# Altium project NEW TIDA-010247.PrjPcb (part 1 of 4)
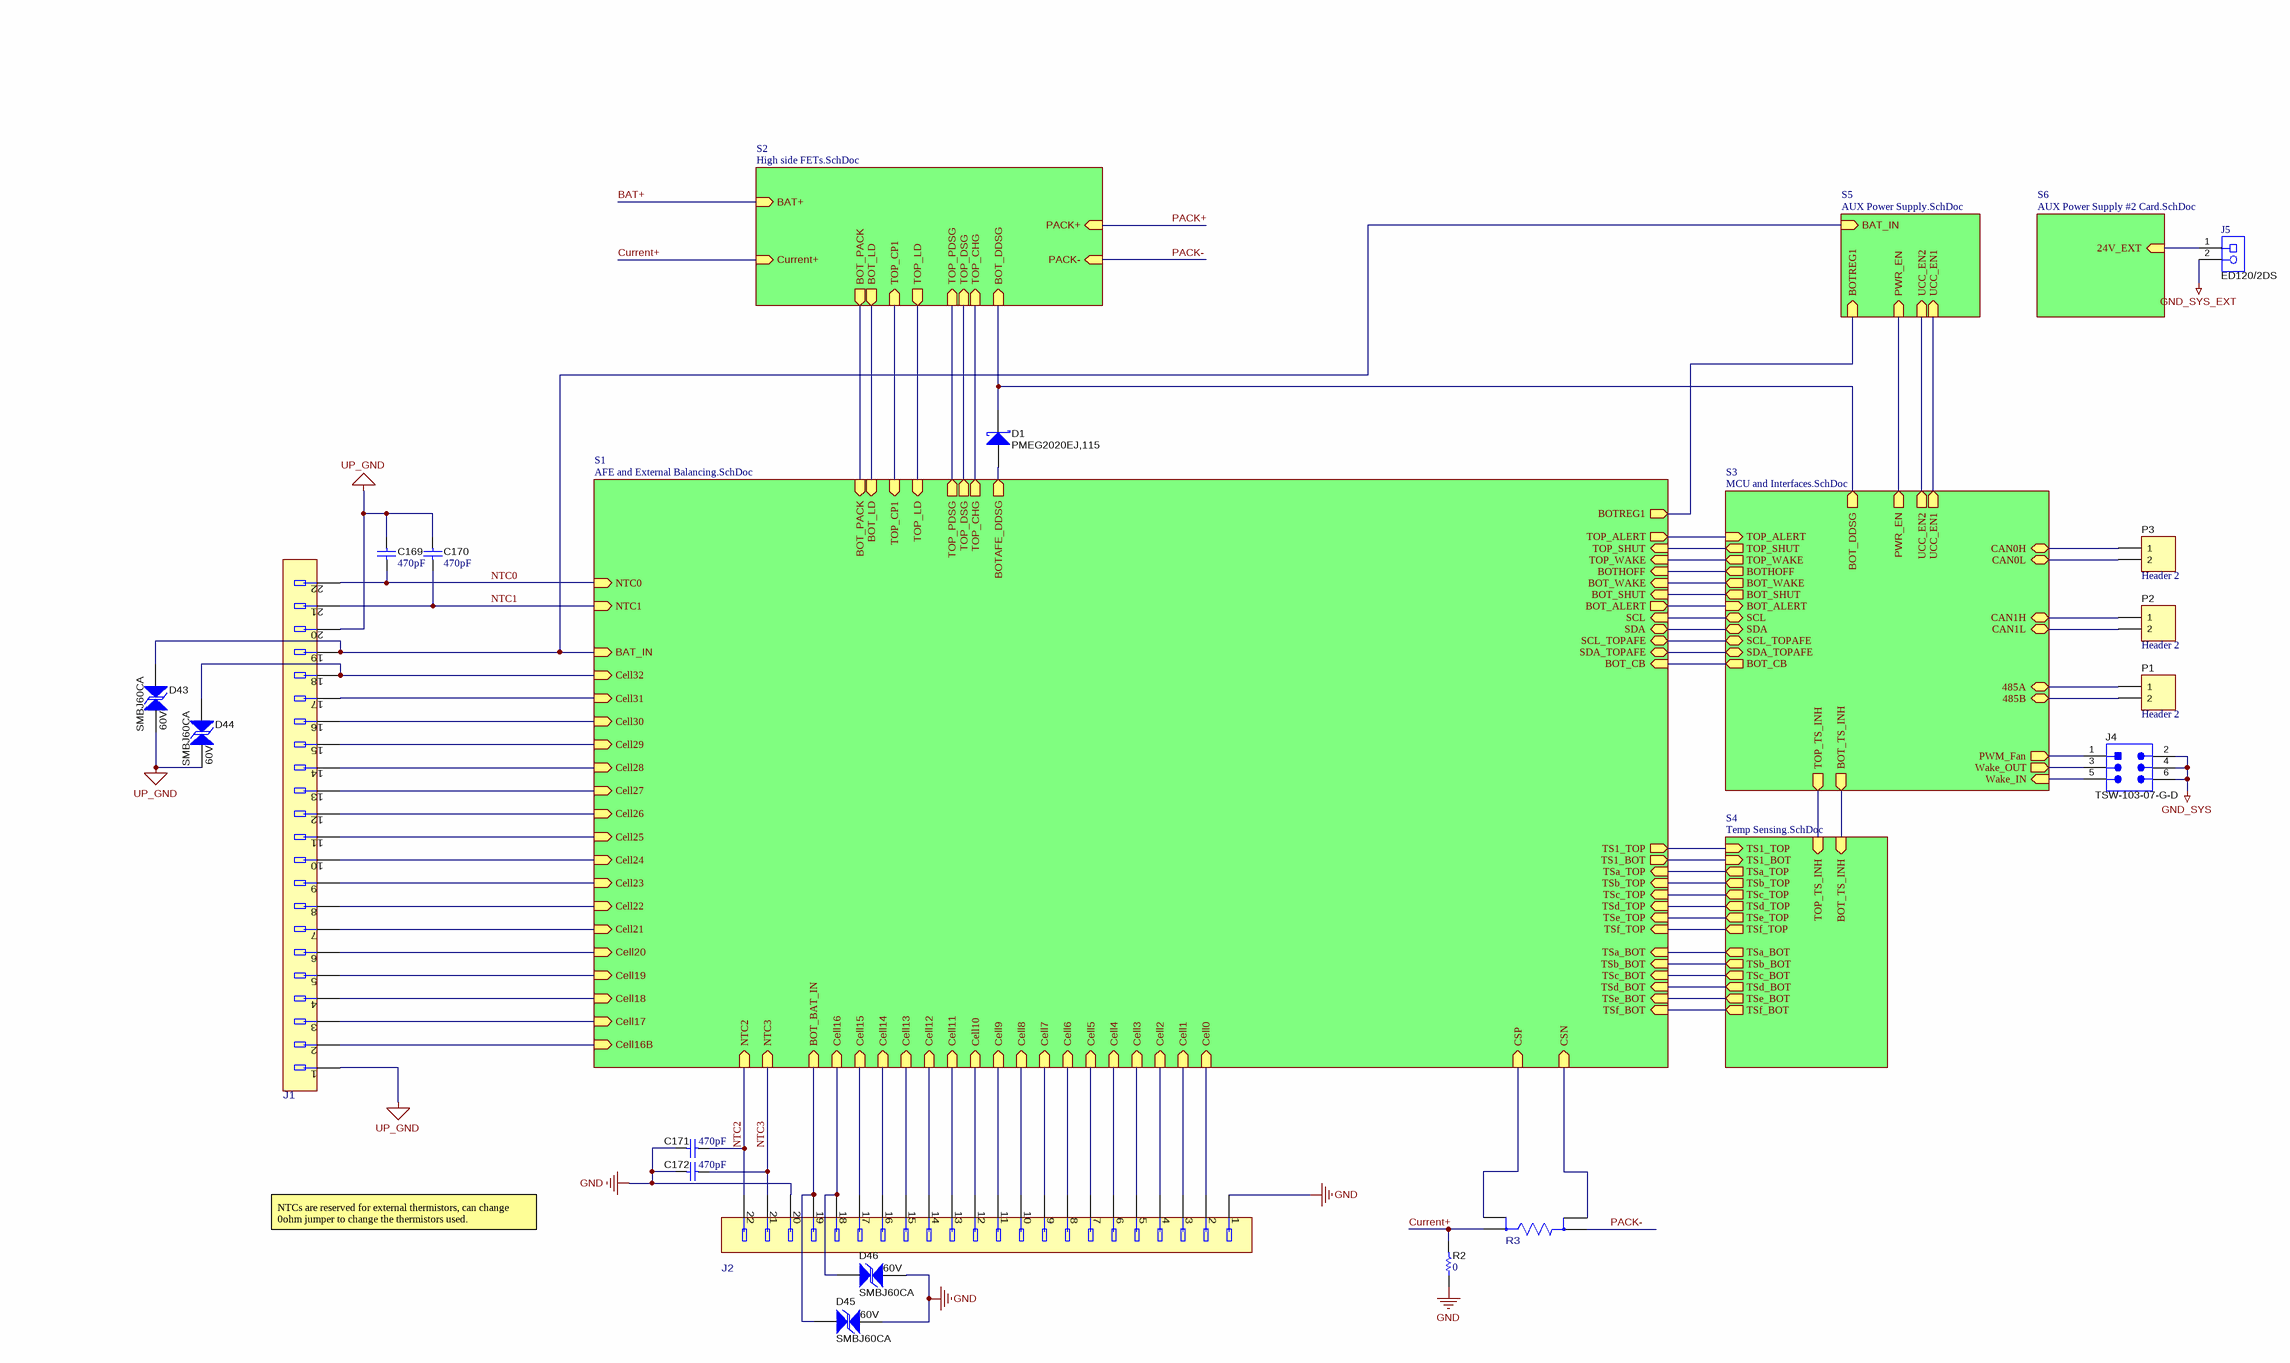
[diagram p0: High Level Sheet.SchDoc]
TID: TIDA-010247; TechSupport: http://www.ti.com/support; SCH_Rev: E1; PRJ_Title: 48v-1500v stackable BMU; PRJ_Number: TIDA-010247; PRJ_Engineer: Kian Lin; PRJ_Customer: Public Release; PCB_Rev: E1; PCB_Layout: Kian Lin; CopyrightYear: 2018
10 sheets, 812 parts. Net scope: hierarchical (ports join the sheet entries above them; power ports are global).
Board file: 32S BMU_BQ76972_CAN Stacking_V2.PcbDoc
Sheets:
  High Level Sheet.SchDoc
    S3 = MCU and Interfaces.SchDoc
    S1 = AFE and External Balancing.SchDoc
    S2 = High side FETs.SchDoc
    S5 = AUX Power Supply.SchDoc
    S4 = Temp Sensing.SchDoc
    U_EVM_Hardware = EVM_Hardware.SchDoc
    S6 = AUX Power Supply #2 Card.SchDoc
    S8 = Cell simulator.SchDoc
    S9 = Cover Sheet.SchDoc

## Sheet High Level Sheet.SchDoc
size A2; Date: Not shown in title block; ApprovedBy: Not shown in title block; CheckedBy: Not shown in title block; Author: Not shown in title block; CompanyName: Not shown in title block; Engineer: Not shown in title block; Organization: Not shown in title block; Address1: Not shown in title block; Address2: Not shown in title block; Address3: Not shown in title block; Address4: Not shown in title block; DocumentNumber: 1; Revision: Use project parameter SCH_Rev; SheetNumber: 1; SheetTotal: 10; PageSetup: Record=PageOptions¦CenterHorizontal=True¦CenterVertical=True¦PrintScale=0.69¦XCorrection=1.00¦YCorrection=1.00¦PrintKind=0¦BorderSize=5000000¦LeftOffset=0¦BottomOffset=0¦Orientation=2¦PaperLength=1000¦PaperWidth=1000¦Scale=100¦PaperSource=15¦PrintQuality=600¦MediaType=1¦DitherType=10¦PaperKind=Letter¦PrintScaleMode=1

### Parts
C169  ValueDisplayed: 470pF  [0201]  (hidden comment: GRM033R71C471KA01D)
C170  ValueDisplayed: 470pF  [0201]  (hidden comment: GRM033R71C471KA01D)
C171  ValueDisplayed: 470pF  [0201]  (hidden comment: GRM033R71C471KA01D)
C172  ValueDisplayed: 470pF  [0201]  (hidden comment: GRM033R71C471KA01D)
D1  PMEG2020EJ,115  [SOD-323F]  (no BOM)
D43  SMBJ60CA  value 60V  [SMB-Bi]
D44  SMBJ60CA  value 60V  [SMB-Bi]
D45  SMBJ60CA  value 60V  [SMB-Bi]
D46  SMBJ60CA  value 60V  [SMB-Bi]
J1  705550056  [FP-705550056_HDR22-MFG]  (value not drawn)
J2  705550056  [FP-705550056_HDR22-MFG]  (value not drawn)
J4  TSW-103-07-G-D  [TSW-103-07-G-D]
J5  ED120/2DS  [On-Shore_ED120_2DS]
P1  Header 2  [HDR1X2]  (no BOM)
P2  Header 2  [HDR1X2]  (no BOM)
P3  Header 2  [HDR1X2]  (no BOM)
R2  ValueDisplayed: 0  [0603]  (hidden comment: CRCW06030000Z0EA)
R3  SEWF3951FL300PT  [FP-SEWF3951FL300PT_3951-MFG]  (value not drawn)

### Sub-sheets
S1 = AFE and External Balancing.SchDoc: BAT_IN (in), BOT_LD (in), BOT_PACK (in), TOP_PDSG (out), TOP_DSG (out), TOP_CHG (out), TOP_LD (in), BOTAFE_DDSG (out), TOP_CP1 (in), SDA (bidir), SCL (in), BOT_SHUT (in), BOT_WAKE (in), BOTHOFF (in), TOP_WAKE (in), TOP_SHUT (in), SCL_TOPAFE (bidir), SDA_TOPAFE (bidir), TOP_ALERT (out), BOT_ALERT (out), Cell20 (in), Cell19 (in), Cell22 (in), Cell24 (in), Cell21 (in), Cell23 (in), Cell25 (in), Cell26 (in), Cell27 (in), Cell28 (in), Cell29 (in), Cell17 (in), Cell18 (in), Cell16B (in), NTC0 (in), NTC1 (in), Cell30 (in), Cell31 (in), Cell32 (in), BOT_BAT_IN (in), Cell15 (in), Cell3 (in), Cell6 (in), Cell11 (in), Cell7 (in), Cell12 (in), Cell9 (in), Cell4 (in), Cell8 (in), Cell5 (in), Cell13 (in), Cell14 (in), Cell16 (in), Cell10 (in), Cell0 (in), Cell1 (in), Cell2 (in), NTC3 (in), NTC2 (in), CSP (in), CSN (in), BOTREG1 (out), TSa_TOP (in), TS1_TOP (out), TS1_BOT (out), TSe_BOT (in), TSf_BOT (in), TSd_BOT (in), TSc_BOT (in), TSb_BOT (in), TSa_BOT (in), TSc_TOP (in), TSb_TOP (in), TSf_TOP (in), TSd_TOP (in), TSe_TOP (in), BOT_CB (in)
S2 = High side FETs.SchDoc: BAT+ (in), Current+ (in), PACK+ (in), PACK- (in), BOT_LD (out), BOT_PACK (out), TOP_DSG (in), TOP_LD (out), TOP_CHG (in), BOT_DDSG (in), TOP_PDSG (in), TOP_CP1 (in)
S3 = MCU and Interfaces.SchDoc: PWR_EN (out), BOT_DDSG (out), TOP_ALERT (in), TOP_SHUT (out), TOP_WAKE (out), BOTHOFF (out), BOT_WAKE (out), BOT_SHUT (out), SCL_TOPAFE (bidir), SDA_TOPAFE (bidir), PWM_Fan (out), Wake_IN (in), Wake_OUT (out), SCL (bidir), SDA (bidir), BOT_TS_INH (out), TOP_TS_INH (out), BOT_ALERT (in), CAN0H (bidir), CAN0L (bidir), CAN1H (bidir), CAN1L (bidir), 485A (bidir), 485B (bidir), BOT_CB (out), UCC_EN2 (out), UCC_EN1 (out)
S4 = Temp Sensing.SchDoc: TOP_TS_INH (in), BOT_TS_INH (in), TSa_TOP (out), TSb_TOP (out), TSc_TOP (out), TSd_TOP (out), TSe_TOP (out), TSf_TOP (out), TSa_BOT (out), TSb_BOT (out), TSc_BOT (out), TSd_BOT (out), TSe_BOT (out), TSf_BOT (out), TS1_TOP (in), TS1_BOT (in)
S5 = AUX Power Supply.SchDoc: BAT_IN (in), PWR_EN (in), UCC_EN1 (in), UCC_EN2 (in), BOTREG1 (in)
S6 = AUX Power Supply #2 Card.SchDoc: 24V_EXT (in)
S8 = Cell simulator.SchDoc: no entries
S9 = Cover Sheet.SchDoc: no entries
U_EVM_Hardware = EVM_Hardware.SchDoc: no entries

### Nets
GND: C171.2 C172.2 D45.1 D46.1 J2.1 J2.20 R2.1
GND_SYS: J4.2 J4.4 J4.6
GND_SYS_EXT: J5.2
UP_GND: C169.2 C170.2 D43.1 D44.1 J1.1 J1.20
5V: sheet S1/BOTREG1, sheet S5/BOTREG1
24V_EXT: J5.1 ; sheet S6/24V_EXT
485A: P1.1 ; sheet S3/485A
485B: P1.2 ; sheet S3/485B
BAT_IN: D43.2 J1.19 ; sheet S1/BAT_IN, sheet S5/BAT_IN
BOT_ALERT: sheet S3/BOT_ALERT, sheet S1/BOT_ALERT
BOT_BAT_IN: D45.2 J2.19 ; sheet S1/BOT_BAT_IN
BOT_CB: sheet S3/BOT_CB, sheet S1/BOT_CB
BOT_DDSG: D1.1(K) ; sheet S3/BOT_DDSG, sheet S2/BOT_DDSG
BOT_INH: sheet S3/BOT_TS_INH, sheet S4/BOT_TS_INH
BOT_LD: sheet S1/BOT_LD, sheet S2/BOT_LD
BOT_PACK: sheet S1/BOT_PACK, sheet S2/BOT_PACK
BOT_SHUT: sheet S3/BOT_SHUT, sheet S1/BOT_SHUT
BOT_WAKE: sheet S3/BOT_WAKE, sheet S1/BOT_WAKE
BOTAFE_DDSG: D1.2(A) ; sheet S1/BOTAFE_DDSG
BOTHOFF: sheet S3/BOTHOFF, sheet S1/BOTHOFF
CAN0H: P3.1 ; sheet S3/CAN0H
CAN0L: P3.2 ; sheet S3/CAN0L
CAN1H: P2.1 ; sheet S3/CAN1H
CAN1L: P2.2 ; sheet S3/CAN1L
Cell0: J2.2 ; sheet S1/Cell0
Cell1: J2.3 ; sheet S1/Cell1
Cell2: J2.4 ; sheet S1/Cell2
Cell3: J2.5 ; sheet S1/Cell3
Cell4: J2.6 ; sheet S1/Cell4
Cell5: J2.7 ; sheet S1/Cell5
Cell6: J2.8 ; sheet S1/Cell6
Cell7: J2.9 ; sheet S1/Cell7
Cell8: J2.10 ; sheet S1/Cell8
Cell9: J2.11 ; sheet S1/Cell9
Cell10: J2.12 ; sheet S1/Cell10
Cell11: J2.13 ; sheet S1/Cell11
Cell12: J2.14 ; sheet S1/Cell12
Cell13: J2.15 ; sheet S1/Cell13
Cell14: J2.16 ; sheet S1/Cell14
Cell15: J2.17 ; sheet S1/Cell15
Cell16: D46.2 J2.18 ; sheet S1/Cell16
Cell16B: J1.2 ; sheet S1/Cell16B
Cell17: J1.3 ; sheet S1/Cell17
Cell18: J1.4 ; sheet S1/Cell18
Cell19: J1.5 ; sheet S1/Cell19
Cell20: J1.6 ; sheet S1/Cell20
Cell21: J1.7 ; sheet S1/Cell21
Cell22: J1.8 ; sheet S1/Cell22
Cell23: J1.9 ; sheet S1/Cell23
Cell24: J1.10 ; sheet S1/Cell24
Cell25: J1.11 ; sheet S1/Cell25
Cell26: J1.12 ; sheet S1/Cell26
Cell27: J1.13 ; sheet S1/Cell27
Cell28: J1.14 ; sheet S1/Cell28
Cell29: J1.15 ; sheet S1/Cell29
Cell30: J1.16 ; sheet S1/Cell30
Cell31: J1.17 ; sheet S1/Cell31
Cell32: D44.2 J1.18 ; sheet S1/Cell32
CSN: R3.4 ; sheet S1/CSN
CSP: R3.3 ; sheet S1/CSP
Current+: R2.2 R3.1 ; sheet S2/Current+
EN: sheet S3/PWR_EN, sheet S5/PWR_EN
NTC0: C169.1 J1.22 ; sheet S1/NTC0
NTC1: C170.1 J1.21 ; sheet S1/NTC1
NTC2: C171.1 J2.22 ; sheet S1/NTC2
NTC3: C172.1 J2.21 ; sheet S1/NTC3
PACK-: R3.2 ; sheet S2/PACK-
PWM_Fan: J4.1 ; sheet S3/PWM_Fan
SCL: sheet S3/SCL, sheet S1/SCL
SCL_TOPAFE: sheet S3/SCL_TOPAFE, sheet S1/SCL_TOPAFE
SDA: sheet S3/SDA, sheet S1/SDA
SDA_TOPAFE: sheet S3/SDA_TOPAFE, sheet S1/SDA_TOPAFE
TOP_ALERT: sheet S3/TOP_ALERT, sheet S1/TOP_ALERT
TOP_CHG: sheet S1/TOP_CHG, sheet S2/TOP_CHG
TOP_CP1: sheet S1/TOP_CP1, sheet S2/TOP_CP1
TOP_DSG: sheet S1/TOP_DSG, sheet S2/TOP_DSG
TOP_LD: sheet S1/TOP_LD, sheet S2/TOP_LD
TOP_PDSG: sheet S1/TOP_PDSG, sheet S2/TOP_PDSG
TOP_SHUT: sheet S3/TOP_SHUT, sheet S1/TOP_SHUT
TOP_TS_INH: sheet S3/TOP_TS_INH, sheet S4/TOP_TS_INH
TOP_WAKE: sheet S3/TOP_WAKE, sheet S1/TOP_WAKE
TS1_BOT: sheet S1/TS1_BOT, sheet S4/TS1_BOT
TS1_TOP: sheet S1/TS1_TOP, sheet S4/TS1_TOP
TSa_BOT: sheet S1/TSa_BOT, sheet S4/TSa_BOT
TSa_TOP: sheet S1/TSa_TOP, sheet S4/TSa_TOP
TSb_BOT: sheet S1/TSb_BOT, sheet S4/TSb_BOT
TSb_TOP: sheet S1/TSb_TOP, sheet S4/TSb_TOP
TSc_BOT: sheet S1/TSc_BOT, sheet S4/TSc_BOT
TSc_TOP: sheet S1/TSc_TOP, sheet S4/TSc_TOP
TSd_BOT: sheet S1/TSd_BOT, sheet S4/TSd_BOT
TSd_TOP: sheet S1/TSd_TOP, sheet S4/TSd_TOP
TSe_BOT: sheet S1/TSe_BOT, sheet S4/TSe_BOT
TSe_TOP: sheet S1/TSe_TOP, sheet S4/TSe_TOP
TSf_BOT: sheet S1/TSf_BOT, sheet S4/TSf_BOT
TSf_TOP: sheet S1/TSf_TOP, sheet S4/TSf_TOP
UCC_EN1: sheet S3/UCC_EN1, sheet S5/UCC_EN1
UCC_EN2: sheet S3/UCC_EN2, sheet S5/UCC_EN2
Wake_IN: J4.5 ; sheet S3/Wake_IN
Wake_OUT: J4.3 ; sheet S3/Wake_OUT

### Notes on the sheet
- NTCs are reserved for external thermistors, can change 0ohm jumper to change the thermistors used.

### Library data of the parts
C169-C172 = CMP-0009758-1: CAP, CERM, 470 pF, 16 V, +/- 10%, X7R, 0201; Manufacturer: MuRata; TaMin_C: -55°C; Polarized: N; SizeAreaWB_mm2: 2.08; Value1: Unknown; U/M: EA; Value: 470pF; TaMax_C: 125°C; SizeZ_mm: 0.26; SizeX_mm: 0.6; SizeY_mm: 0.3; Value2: 16V; SizeArea_mm2: 0.18; VDC_V: ; AEC Category: Q200
D1 = CMP-0077073-2: Diode, Schottky, 20 V, 2 A, SOD-323F; Manufacturer: Nexperia; Value2: 0.525V; Value1: 2A; Green_REACh: Incomplete; Value: 20V; SizeX_mm: 2.5; SizeAreaWB_mm2: 7.875; AEC Category: Q101; Vf_V: 525mV; SizeY_mm: 1.25; SizeArea_mm2: 3.125; SizeZ_mm: 0.8; Green_Lifecycle: Not Set; TJmax_C: 150°C; AEC Qualified: N
D43-D46 = CMP-0006055-3: Diode, TVS, Bi, 60V， SMB; Manufacturer: Littelfuse; AEC Category: Q101; AEC Qualified: N; Vbr_Max: 62.7V; Value1: 600W; Vbr_Min: 56.7V; Vc: 82.4V; VRWM: 51V; Ipp: 7.3A
J1 J2 = CMP-0087165-1: Connector Header Through Hole, Right Angle 22 position 0.100" (2.54mm); Manufacturer: Molex; Voltage_V: 250V; Current_A: 3A; ContactFinish: Gold,Nickel; Row_Count: 1
J4 = CMP-0075406-2: Header, 100mil, 3x2, Gold, TH; Manufacturer: Samtec; Pitch_mm: 2.54; Cert_VDE: N; Gender: Male; Cert_CSA: Y; Voltage_V: 550V; Green_REACh: Passed; Current_A: 6.3A; Green_Lifecycle: Active; Row_Count: 2
J5 = CMP-0074910-1: Terminal Block, 5.08 mm, 2x1, Brass, TH; Manufacturer: On-Shore Technology; Cert_VDE: Y; CNHeader: False; Current_A: 15A; Green_Lifecycle: Not Set; Shrouded: N; Gender: Female; Green_REACh: Incomplete; Voltage_V: 300V; Row_Count: 1; Pitch_mm: 5.08; CT: True
P1-P3 = Header 2: Header, 2-Pin
R2 = CMP-0025697-4: RES, 0, 5%, 0.1 W, AEC-Q200 Grade 0, 0603; Manufacturer: Vishay-Dale; Power_W: 100mW; TempCo: 200 ppm/C; Value_Code: 0000; Value: 0; EIA_Code: E24; SizeX_mm: 1.6; SizeY_mm: 0.8; SizeZ_mm: 1; Value2: 0.1W; SizeArea_mm2: 1.28; AEC Qualified: Y; VDC_V: 75V; AEC Category: Q200
R3 = CMP-0122174-1: High-Precision Low-TCR Alloy Current Sensing Resistor 0.3mOhm 1% 25ppm/°C 15W 3951; Manufacturer: C&B ELECTRONICS; AEC Grade: Grade 0; AEC Qualified: Yes; Res_ohm: 300µ; SizeZ_mm: 2.6mm; Value: 300µ

## Sheet MCU and Interfaces.SchDoc
size A2; Date: Not shown in title block; ApprovedBy: Not shown in title block; CheckedBy: Not shown in title block; Author: Not shown in title block; CompanyName: Not shown in title block; Engineer: Not shown in title block; Organization: Not shown in title block; Address1: Not shown in title block; Address2: Not shown in title block; Address3: Not shown in title block; Address4: Not shown in title block; DocumentNumber: 1; Revision: Use project parameter SCH_Rev; SheetNumber: 4; SheetTotal: 10; PageSetup: Record=PageOptions¦CenterHorizontal=True¦CenterVertical=True¦PrintScale=0.69¦XCorrection=1.00¦YCorrection=1.00¦PrintKind=0¦BorderSize=5000000¦LeftOffset=0¦BottomOffset=0¦Orientation=2¦PaperLength=1000¦PaperWidth=1000¦Scale=100¦PaperSource=15¦PrintQuality=600¦MediaType=1¦DitherType=10¦PaperKind=Letter¦PrintScaleMode=1
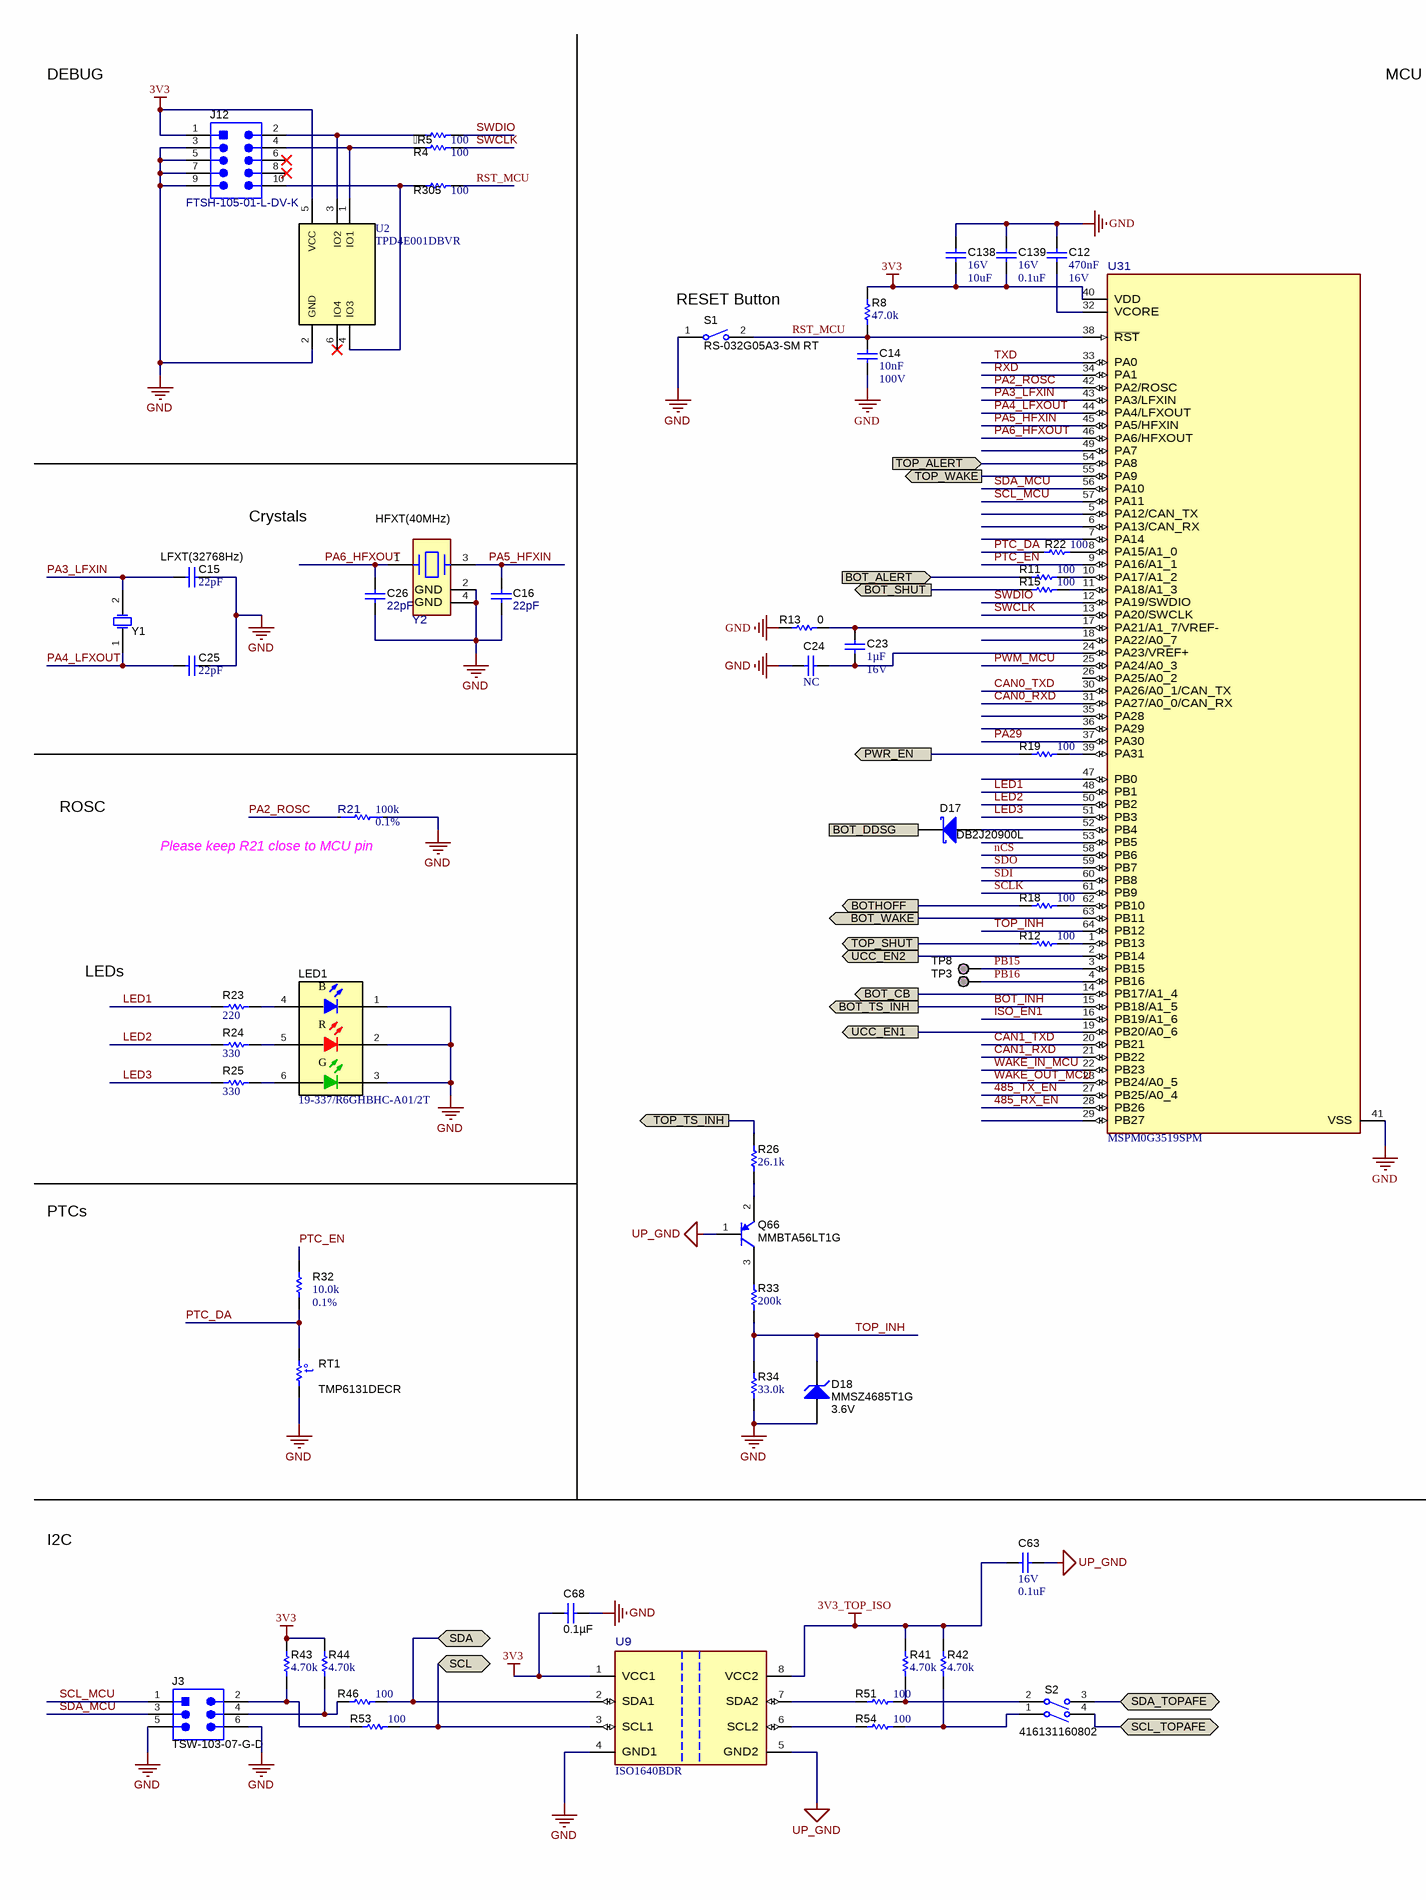
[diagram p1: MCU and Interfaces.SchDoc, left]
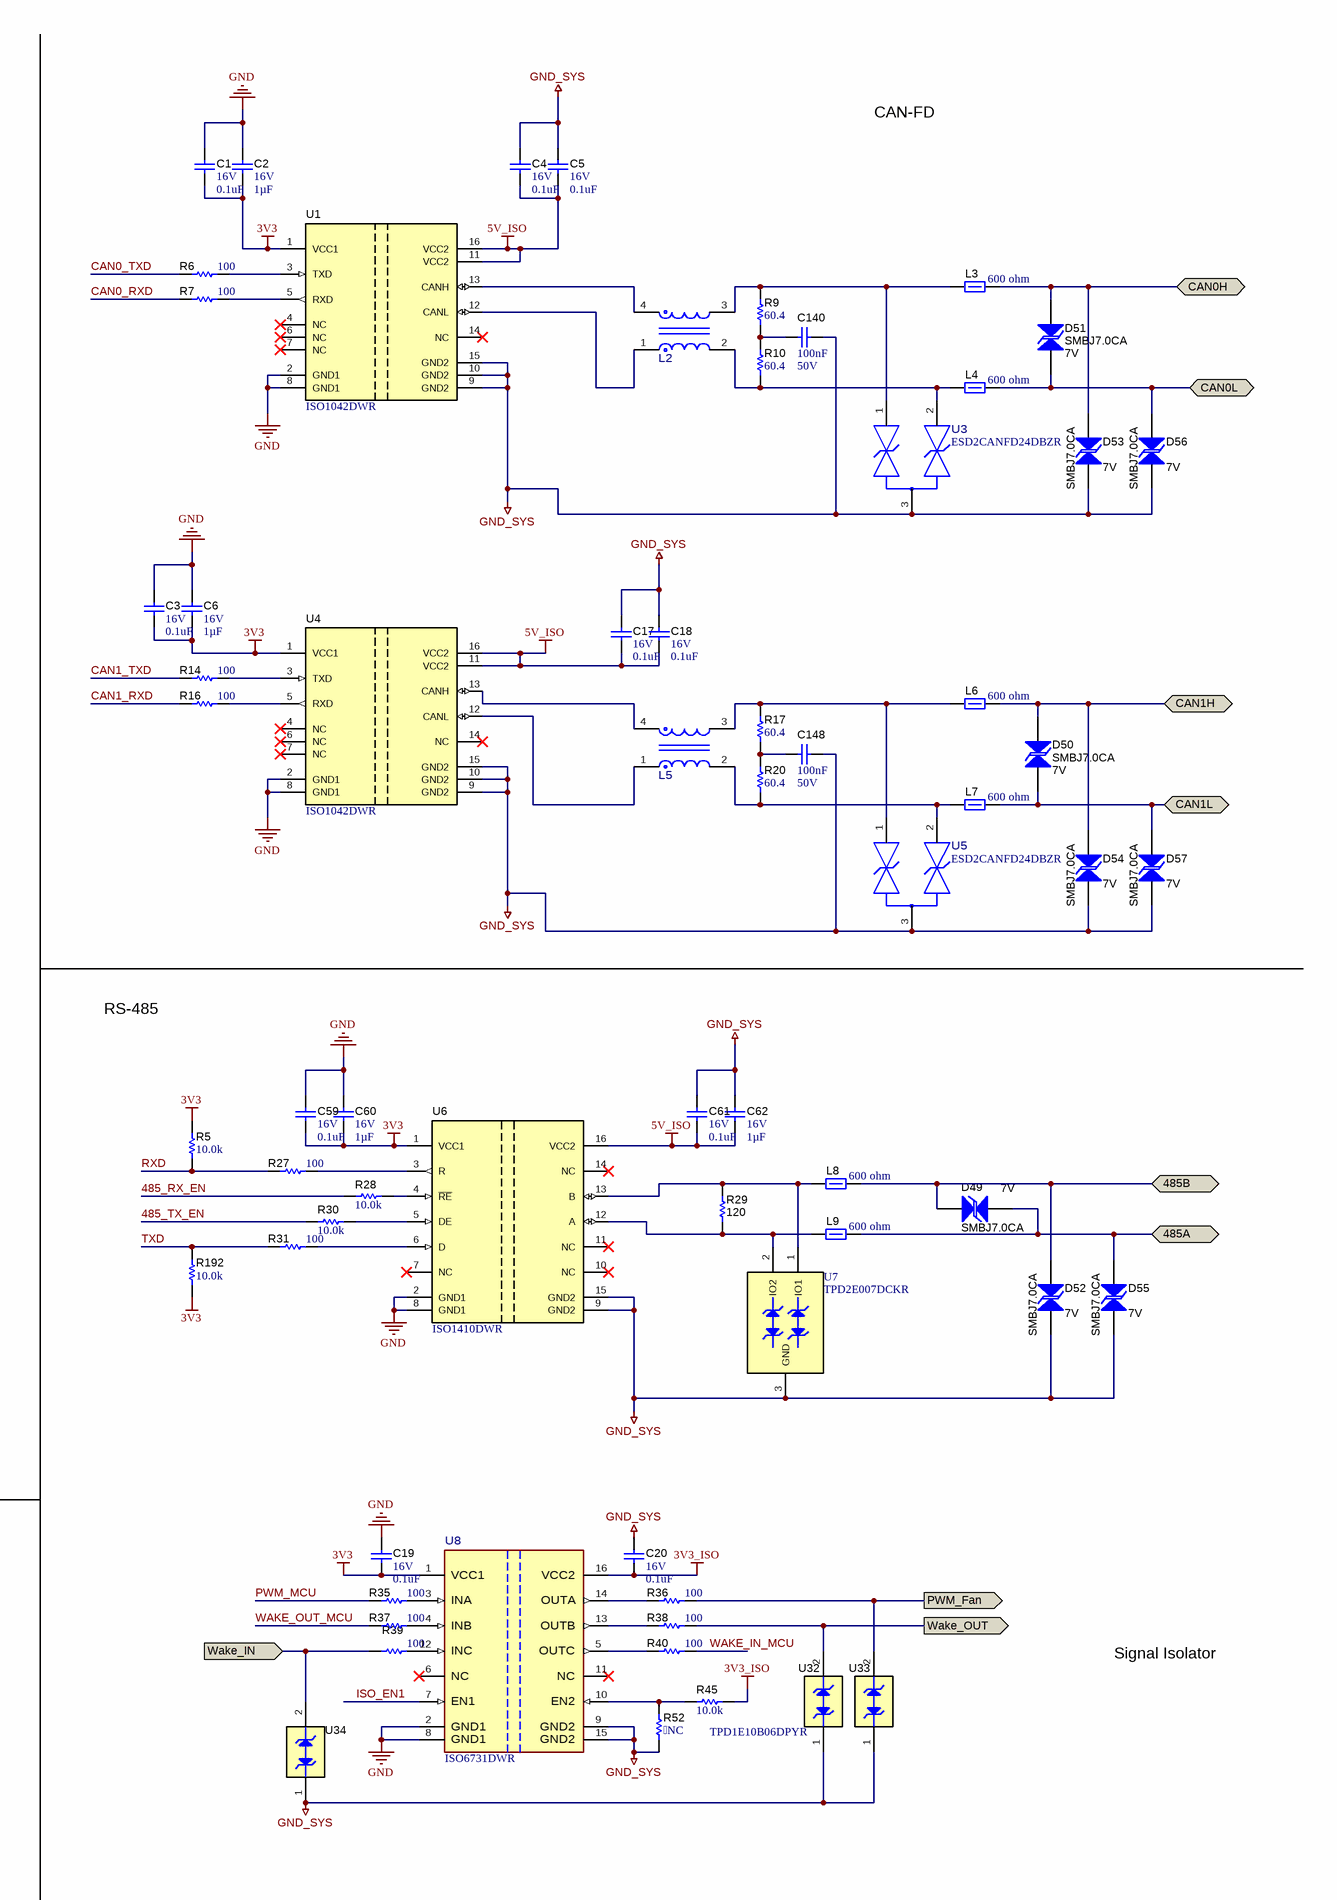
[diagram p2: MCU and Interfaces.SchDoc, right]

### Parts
R5  ValueDisplayed: 100  [0603]  (hidden comment: CRCW0603100RFKEA)
C1  VDC_V: 16V  ValueDisplayed: 0.1uF  [0603]  (hidden comment: GRM188R61C104KA01D)
C2  VDC_V: 16V  ValueDisplayed: 1µF  [0603]  (hidden comment: CC0603MRX5R7BB105)
C3  VDC_V: 16V  ValueDisplayed: 0.1uF  [0603]  (hidden comment: EMK107BBJ106MA-T)
C4  VDC_V: 16V  ValueDisplayed: 0.1uF  [0603]  (hidden comment: GRM188R61C104KA01D)
C5  VDC_V: 16V  ValueDisplayed: 0.1uF  [0603]  (hidden comment: GRM188R61C104KA01D)
C6  VDC_V: 16V  ValueDisplayed: 1µF  [0603]  (hidden comment: EMK107BBJ106MA-T)
C12  Cap_F: 470nF  VDC_V: 16V  [0603]  (hidden comment: GCM188R71C474KA55D)
C14  Cap_F: 10nF  VDC_V: 100V  [0603]  (hidden comment: C0603X103K1RACTU)
C15  ValueDisplayed: 22pF  [0402]  (hidden comment: GRM1555C1H220JA01D)
C16  ValueDisplayed: 22pF  [0402]  (hidden comment: GRM1555C1H220JA01D)
C17  VDC_V: 16V  ValueDisplayed: 0.1uF  [0603]  (hidden comment: GRM188R61C104KA01D)
C18  VDC_V: 16V  ValueDisplayed: 0.1uF  [0603]  (hidden comment: GRM188R61C104KA01D)
C19  VDC_V: 16V  ValueDisplayed: 0.1uF  [0603]  (hidden comment: GRM188R61C104KA01D)
C20  VDC_V: 16V  ValueDisplayed: 0.1uF  [0603]  (hidden comment: GRM188R61C104KA01D)
C23  Cap_F: 1µF  VDC_V: 16V  [0603]  (hidden comment: GCM188R71C105KA64J)
C24  ValueDisplayed: NC  [0603]  (hidden comment: C1608X5R1E105K080AC)  (no BOM)
C25  ValueDisplayed: 22pF  [0402]  (hidden comment: GRM1555C1H220JA01D)
C26  ValueDisplayed: 22pF  [0402]  (hidden comment: GRM1555C1H220JA01D)
C59  VDC_V: 16V  ValueDisplayed: 0.1uF  [0603]  (hidden comment: GRM188R61C104KA01D)
C60  VDC_V: 16V  ValueDisplayed: 1µF  [0603]  (hidden comment: CC0603MRX5R7BB105)
C61  VDC_V: 16V  ValueDisplayed: 0.1uF  [0603]  (hidden comment: GRM188R61C104KA01D)
C62  VDC_V: 16V  ValueDisplayed: 1µF  [0603]  (hidden comment: CC0603MRX5R7BB105)
C63  VDC_V: 16V  ValueDisplayed: 0.1uF  [0603]  (hidden comment: GRM188R61C104KA01D)
C68  ValueDisplayed: 0.1µF  [0402]  (hidden comment: GRM188R71H104KA93D)
C138  VDC_V: 16V  ValueDisplayed: 10uF  [0603]  (hidden comment: EMK107BBJ106MA-T)
C139  VDC_V: 16V  ValueDisplayed: 0.1uF  [0603]  (hidden comment: GRM188R61C104KA01D)
C140  Cap_F: 100nF  VDC_V: 50V  [0603]  (hidden comment: GRM188R71H104KA93D)
C148  Cap_F: 100nF  VDC_V: 50V  [0603]  (hidden comment: GRM188R71H104KA93D)
D17  DB2J20900L  [SOD-323F]
D18  MMSZ4685T1G  value 3.6V  [SOD-123]
D49  SMBJ7.0CA  value 7V  [SMB-Bi]
D50  SMBJ7.0CA  value 7V  [SMB-Bi]
D51  SMBJ7.0CA  value 7V  [SMB-Bi]
D52  SMBJ7.0CA  value 7V  [SMB-Bi]
D53  SMBJ7.0CA  value 7V  [SMB-Bi]
D54  SMBJ7.0CA  value 7V  [SMB-Bi]
D55  SMBJ7.0CA  value 7V  [SMB-Bi]
D56  SMBJ7.0CA  value 7V  [SMB-Bi]
D57  SMBJ7.0CA  value 7V  [SMB-Bi]
J3  TSW-103-07-G-D  [TSW-103-07-G-D]
J12  FTSH-105-01-L-DV-K  [Samtec_FTSH-105-01-x-DV-K]
L2  SRF3225TAC-510Y  [FP-SRF3225TAC-510Y_SMT4-MFG]  (value not drawn)
L3  ValueDisplayed: 600 ohm  [0603]  (hidden comment: 74279265)
L4  ValueDisplayed: 600 ohm  [0603]  (hidden comment: 74279265)
L5  SRF3225TAC-510Y  [FP-SRF3225TAC-510Y_SMT4-MFG]  (value not drawn)
L6  ValueDisplayed: 600 ohm  [0603]  (hidden comment: 74279265)
L7  ValueDisplayed: 600 ohm  [0603]  (hidden comment: 74279265)
L8  ValueDisplayed: 600 ohm  [0603]  (hidden comment: 74279265)
L9  ValueDisplayed: 600 ohm  [0603]  (hidden comment: 74279265)
LED1  19-337/R6GHBHC-A01/2T  [19-337_RGB]
Q66  MMBTA56LT1G  [SOT-23]
R4  ValueDisplayed: 100  [0603]  (hidden comment: CRCW0603100RFKEA)
R5  ValueDisplayed: 10.0k  [0603]  (hidden comment: CRCW060310K0FKEA)
R6  ValueDisplayed: 100  [0603]  (hidden comment: CRCW0603100RFKEA)
R7  ValueDisplayed: 100  [0603]  (hidden comment: CRCW0603100RFKEA)
R8  ValueDisplayed: 47.0k  [0603]  (hidden comment: CRCW060347K0FKEA)
R9  ValueDisplayed: 60.4  [0603]  (hidden comment: RC0603FR-0760R4L)
R10  ValueDisplayed: 60.4  [0603]  (hidden comment: RC0603FR-0760R4L)
R11  ValueDisplayed: 100  [0603]  (hidden comment: CRCW0603100RFKEA)
R12  ValueDisplayed: 100  [0603]  (hidden comment: CRCW0603100RFKEA)
R13  ValueDisplayed: 0  [0603]  (hidden comment: CRCW04020000Z0ED)
R14  ValueDisplayed: 100  [0603]  (hidden comment: CRCW0603100RFKEA)
R15  ValueDisplayed: 100  [0603]  (hidden comment: CRCW0603100RFKEA)
R16  ValueDisplayed: 100  [0603]  (hidden comment: CRCW0603100RFKEA)
R17  ValueDisplayed: 60.4  [0603]  (hidden comment: RC0603FR-0760R4L)
R18  ValueDisplayed: 100  [0603]  (hidden comment: CRCW0603100RFKEA)
R19  ValueDisplayed: 100  [0603]  (hidden comment: CRCW0603100RFKEA)
R20  ValueDisplayed: 60.4  [0603]  (hidden comment: RC0603FR-0760R4L)
R21  Tolerance_%: 0.1%  Res_ohm: 100k  [FP-ERA-2AEB104X_0402-MFG]  (hidden comment: ERA-2AEB104X)
R22  ValueDisplayed: 100  [0603]  (hidden comment: CRCW0603100RFKEA)
R23  ValueDisplayed: 220  [0402]  (hidden comment: CRCW0402220RJNED)
R24  ValueDisplayed: 330  [0402]  (hidden comment: CRCW0402330RJNED)
R25  ValueDisplayed: 330  [0402]  (hidden comment: CRCW0402330RJNED)
R26  ValueDisplayed: 26.1k  [0603]  (hidden comment: CRCW060326K1FKEA)
R27  ValueDisplayed: 100  [0603]  (hidden comment: CRCW0603100RFKEA)
R28  ValueDisplayed: 10.0k  [0603]  (hidden comment: CRCW060310K0FKEA)
R29  ValueDisplayed: 120  [1206]  (hidden comment: RC0603FR-07120RL)
R30  ValueDisplayed: 10.0k  [0603]  (hidden comment: CRCW060310K0FKEA)
R31  ValueDisplayed: 100  [0603]  (hidden comment: CRCW0603100RFKEA)
R32  Value1: 0.1%  ValueDisplayed: 10.0k  [0603]  (hidden comment: RT0603BRD0710KL)
R33  ValueDisplayed: 200k  [0603]  (hidden comment: CRCW0603200KFKEA)
R34  ValueDisplayed: 33.0k  [0603]  (hidden comment: RC0603FR-0733KL)
R35  ValueDisplayed: 100  [0603]  (hidden comment: CRCW0603100RFKEA)
R36  ValueDisplayed: 100  [0603]  (hidden comment: CRCW0603100RFKEA)
R37  ValueDisplayed: 100  [0603]  (hidden comment: CRCW0603100RFKEA)
R38  ValueDisplayed: 100  [0603]  (hidden comment: CRCW0603100RFKEA)
R39  ValueDisplayed: 100  [0603]  (hidden comment: CRCW0603100RFKEA)
R40  ValueDisplayed: 100  [0603]  (hidden comment: CRCW0603100RFKEA)
R41  ValueDisplayed: 4.70k  [0603]  (hidden comment: RC0603FR-074K7L)
R42  ValueDisplayed: 4.70k  [0603]  (hidden comment: RC0603FR-074K7L)
R43  ValueDisplayed: 4.70k  [0603]  (hidden comment: RC0603FR-074K7L)
R44  ValueDisplayed: 4.70k  [0603]  (hidden comment: RC0603FR-074K7L)
R45  ValueDisplayed: 10.0k  [0603]  (hidden comment: CRCW060310K0FKEA)
R46  ValueDisplayed: 100  [0603]  (hidden comment: CRCW0603100RFKEA)
R51  ValueDisplayed: 100  [0603]  (hidden comment: CRCW0603100RFKEA)
R52  ValueDisplayed: NC  [0603]  (hidden comment: CRCW060310K0FKEA)  (no BOM)
R53  ValueDisplayed: 100  [0603]  (hidden comment: CRCW0603100RFKEA)
R54  ValueDisplayed: 100  [0603]  (hidden comment: CRCW0603100RFKEA)
R192  ValueDisplayed: 10.0k  [0603]  (hidden comment: CRCW060310K0FKEA)
R305  ValueDisplayed: 100  [0603]  (hidden comment: CRCW0603100RFKEA)
RT1  TMP6131DECR  [DEC0002A]
S1  RS-032G05A3-SM RT  [SW_RS-032G05A3-SM]
S2  416131160802  [SW_416131160802]
TP3    [TP_SM_1MM]  (value not drawn)  (no BOM)
TP8    [TP_SM_1MM]  (value not drawn)  (no BOM)
U1  ISO1042DWR  [DW0016B_HV]
U2  TPD4E001DBVR  [DBV0006A_L]
U3  PartNumber: ESD2CANFD24DBZR  [DBZ0003A-MFG]  (hidden comment: ESD2CAN24DBZR)
U4  ISO1042DWR  [DW0016B_HV]
U5  PartNumber: ESD2CANFD24DBZR  [DBZ0003A-MFG]  (hidden comment: ESD2CAN24DBZR)
U6  ISO1410DWR  [DW0016B_HV]
U7  TPD2E007DCKR  [DCK0003A_L]
U8  ISO6731DWR  [DW0016A-MFG]
U9  ISO1640BDR  [D0008A-MFG]
U31  MSPM0G3519SPM  [PM0064A-MFG]
U32  TPD1E10B06DPYR  [DPY0002A]
U33  TPD1E10B06DPYR  [DPY0002A]  (value not drawn)
U34  TPD1E10B06DPYR  [DPY0002A]  (value not drawn)
Y1  X1A0001410014  [Epson_FC-135]  (value not drawn)
Y2  X1E0000210179  [FP-X1E0000210179_TSX-3225-MFG]  (value not drawn)

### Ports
485A (bidir), 485B (bidir), BOT_ALERT (in), BOT_CB (out), BOT_DDSG (out), BOT_SHUT (out), BOT_TS_INH (out), BOT_WAKE (out), BOTHOFF (out), CAN0H (bidir), CAN0L (bidir), CAN1H (bidir), CAN1L (bidir), PWM_Fan (out), PWR_EN (out), SCL (bidir), SCL_TOPAFE (bidir), SDA (bidir), SDA_TOPAFE (bidir), TOP_ALERT (in), TOP_SHUT (out), TOP_TS_INH (out), TOP_WAKE (out), UCC_EN1 (out), UCC_EN2 (out), Wake_IN (in), Wake_OUT (out)

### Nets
3V3: C1.1 C2.1 C3.1 C6.1 C19.2 C59.1 C60.1 C68.1 C138.1 C139.1 J12.1 R5.2 R8.2 R43.2 R44.2 R192.1 U1.1(VCC1) U2.5(VCC) U4.1(VCC1) U6.1(VCC1) U8.1(VCC1) U9.1(VCC1) U31.40(VDD)
3V3_ISO: C20.2 R45.2 U8.16(VCC2)
3V3_TOP_ISO: C63.2 R41.2 R42.2 U9.8(VCC2)
5V_ISO: C4.1 C5.1 C17.1 C18.1 C61.1 C62.1 U1.11(VCC2) U1.16(VCC2) U4.11(VCC2) U4.16(VCC2) U6.16(VCC2)
GND: C1.2 C2.2 C3.2 C6.2 C12.1 C14.2 C15.1 C16.2 C19.1 C24.2 C25.1 C26.2 C59.2 C60.2 C68.2 C138.2 C139.2 D18.2(A) J3.5 J3.6 J12.3 J12.5 J12.7 J12.9 LED1.1(K) LED1.2(K) LED1.3(K) R13.1 R21.2 R34.1 RT1.1 S1.1 U1.2(GND1) U1.8(GND1) U2.2(GND) U4.2(GND1) U4.8(GND1) U6.2(GND1) U6.8(GND1) U8.2(GND1) U8.8(GND1) U9.4(GND1) U31.41(VSS) Y2.2(GND) Y2.4(GND)
GND_SYS: C4.2 C5.2 C17.2 C18.2 C20.1 C61.2 C62.2 C140.1 C148.1 D52.1 D53.1 D54.1 D55.1 D56.1 D57.1 R52.1 U1.9(GND2) U1.10(GND2) U1.15(GND2) U3.3(GND) U4.9(GND2) U4.10(GND2) U4.15(GND2) U5.3(GND) U6.9(GND2) U6.15(GND2) U7.3(GND) U8.9(GND2) U8.15(GND2) U32.1(K) U33.1(K) U34.1(K)
UP_GND: C63.1 Q66.1(B) U9.5(GND2)
485_RX_EN: R28.1 U31.28(PB26)
485_TX_EN: R30.1 U31.27(PB25/A0_4)
485A: D49.1 D55.2 L9.2 ; port 485A
485B: D49.2 D52.2 L8.2 ; port 485B
BOT_ALERT: R11.1 ; port BOT_ALERT
BOT_CB: U31.14(PB17/A1_4) ; port BOT_CB
BOT_DDSG: D17.1(K) ; port BOT_DDSG
BOT_INH: U31.15(PB18/A1_5) ; port BOT_TS_INH
BOT_SHUT: R15.1 ; port BOT_SHUT
BOT_WAKE: U31.63(PB11) ; port BOT_WAKE
BOTHOFF: R18.1 ; port BOTHOFF
CAN0_RXD: R7.1 U31.31(PA27/A0_0/CAN_RX)
CAN0_TXD: R6.1 U31.30(PA26/A0_1/CAN_TX)
CAN0H: D51.1 D53.2 L3.2 ; port CAN0H
CAN0L: D51.2 D56.2 L4.2 ; port CAN0L
CAN1_RXD: R16.1 U31.21(PB22)
CAN1_TXD: R14.1 U31.20(PB21)
CAN1H: D50.1 D54.2 L6.2 ; port CAN1H
CAN1L: D50.2 D57.2 L7.2 ; port CAN1L
EN: R19.1 ; port PWR_EN
ISO_EN1: U8.7(EN1) U31.16(PB19/A1_6)
LED1: R23.1 U31.48(PB1)
LED2: R24.1 U31.50(PB2)
LED3: R25.1 U31.51(PB3)
nCS: U31.58(PB6)
PA2_ROSC: R21.1 U31.42(PA2/ROSC)
PA3_LFXIN: C15.2 U31.43(PA3/LFXIN) Y1.2(OSC2)
PA4_LFXOUT: C25.2 U31.44(PA4/LFXOUT) Y1.1(OSC1)
PA5_HFXIN: C16.1 U31.45(PA5/HFXIN) Y2.3
PA6_HFXOUT: C26.1 U31.46(PA6/HFXOUT) Y2.1
PA29: U31.37(PA30)
PB15: TP8.1 U31.3(PB15)
PB16: TP3.1 U31.4(PB16)
PTC_DA: R22.1 R32.1 RT1.2
PTC_EN: R32.2 U31.9(PA16/A1_1)
PWM_Fan: R36.2 U33.2(A) ; port PWM_Fan
PWM_MCU: R35.1 U31.25(PA24/A0_3)
RST_MCU: C14.1 R8.1 R305.2 S1.2 U31.38(~{RST})
RXD: R5.1 R27.1 U31.34(PA1)
SCL: R53.2 U9.3(SCL1) ; port SCL
SCL_MCU: J3.1 U31.57(PA11)
SCL_TOPAFE: S2.4 ; port SCL_TOPAFE
SCLK: U31.61(PB9)
SDA: R46.2 U9.2(SDA1) ; port SDA
SDA_MCU: J3.3 U31.56(PA10)
SDA_TOPAFE: S2.3 ; port SDA_TOPAFE
SDI: U31.60(PB8)
SDO: U31.59(PB7)
SWCLK: R4.2 U31.13(PA20/SWCLK)
SWDIO: R5.2 U31.12(PA19/SWDIO)
TOP_ALERT: U31.54(PA8) ; port TOP_ALERT
TOP_INH: D18.1(K) R33.1 R34.2 U31.64(PB12)
TOP_SHUT: R12.1 ; port TOP_SHUT
TOP_TS_INH: R26.2 ; port TOP_TS_INH
TOP_WAKE: U31.55(PA9) ; port TOP_WAKE
TXD: R31.1 R192.2 U31.33(PA0)
UCC_EN1: U31.19(PB20/A0_6) ; port UCC_EN1
UCC_EN2: U31.2(PB14) ; port UCC_EN2
Wake_IN: R39.1 U34.2(A) ; port Wake_IN
WAKE_IN_MCU: R40.2 U31.22(PB23)
Wake_OUT: R38.2 U32.2(A) ; port Wake_OUT
WAKE_OUT_MCU: R37.1 U31.23(PB24/A0_5)
NetR5_1: R5.1 J12.2 U2.3(IO2)
NetC12_2: C12.2 U31.32(VCORE)
NetC23_1: C23.1 R13.2 U31.17(PA21/A1_7/VREF-)
NetC23_2: C23.2 C24.1 U31.24(PA23/VREF+)
NetC140_2: C140.2 R9.1 R10.2
NetC148_2: C148.2 R17.1 R20.2
NetD17_2: D17.2(A) U31.52(PB4)
NetJ3_2: J3.2 R43.1 R53.1
NetJ3_4: J3.4 R44.1 R46.1
NetJ12_4: J12.4 R4.1 U2.1(IO1)
NetJ12_10: J12.10 R305.1 U2.4(IO3)
NetL2_1: L2.1 U1.12(CANL)
NetL2_2: L2.2 L4.1 R10.1 U3.2(2_IO)
NetL2_3: L2.3 L3.1 R9.2 U3.1(1_IO)
NetL2_4: L2.4 U1.13(CANH)
NetL5_1: L5.1 U4.12(CANL)
NetL5_2: L5.2 L7.1 R20.1 U5.2(2_IO)
NetL5_3: L5.3 L6.1 R17.2 U5.1(1_IO)
NetL5_4: L5.4 U4.13(CANH)
NetL8_1: L8.1 R29.2 U6.13(B) U7.1(IO1)
NetL9_1: L9.1 R29.1 U6.12(A) U7.2(IO2)
NetLED1_4: LED1.4(A) R23.2
NetLED1_5: LED1.5(A) R24.2
NetLED1_6: LED1.6(A) R25.2
NetQ66_2: Q66.2(E) R26.1
NetQ66_3: Q66.3(C) R33.2
NetR6_2: R6.2 U1.3(TXD)
NetR7_2: R7.2 U1.5(RXD)
NetR11_2: R11.2 U31.10(PA17/A1_2)
NetR12_2: R12.2 U31.1(PB13)
NetR14_2: R14.2 U4.3(TXD)
NetR15_2: R15.2 U31.11(PA18/A1_3)
NetR16_2: R16.2 U4.5(RXD)
NetR18_2: R18.2 U31.62(PB10)
NetR19_2: R19.2 U31.39(PA31)
NetR22_2: R22.2 U31.8(PA15/A1_0)
NetR27_2: R27.2 U6.3(R)
NetR28_2: R28.2 U6.4(~{RE})
NetR30_2: R30.2 U6.5(DE)
NetR31_2: R31.2 U6.6(D)
NetR35_2: R35.2 U8.3(INA)
NetR36_1: R36.1 U8.14(OUTA)
NetR37_2: R37.2 U8.4(INB)
NetR38_1: R38.1 U8.13(OUTB)
NetR39_2: R39.2 U8.12(INC)
NetR40_1: R40.1 U8.5(OUTC)
NetR41_1: R41.1 R51.2 S2.2
NetR42_1: R42.1 R54.2 S2.1
NetR45_1: R45.1 R52.2 U8.10(EN2)
NetR51_1: R51.1 U9.7(SDA2)
NetR54_1: R54.1 U9.6(SCL2)

Not connected (* = marked no-connect by the designer): J12 6* 8*; U1 4(NC)* 6(NC)* 7(NC)* 14(NC)*; U2 6(IO4)*; U4 4(NC)* 6(NC)* 7(NC)* 14(NC)*; U6 7(NC)* 10(NC)* 11(NC)* 14(NC)*; U8 6(NC)* 11(NC)*; U31 5(PA12/CAN_TX) 6(PA13/CAN_RX) 7(PA14) 18(PA22/A0_7) 26(PA25/A0_2) 29(PB27) 35(PA28) 36(PA29) 47(PB0) 49(PA7) 53(PB5)

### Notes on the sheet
- DEBUG
- MCU
- CAN-FD
- (near S1) RESET Button
- Crystals
- (near Y2) HFXT(40MHz)
- (near C15) LFXT(32768Hz)
- ROSC
- (near R21) Please keep R21 close to MCU pin
- LEDs
- RS-485
- PTCs
- I2C
- Signal Isolator

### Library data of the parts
R5 R4 R305 = CMP-0021991-4: RES, 100, 1%, 0.1 W, AEC-Q200 Grade 0, 0603; Manufacturer: Vishay-Dale; Power_W: 100mW; TempCo: 100 ppm/C; Value_Code: 100R; Value: 100; EIA_Code: E96; SizeX_mm: 1.6; SizeY_mm: 0.8; SizeZ_mm: 1; Value2: 0.1W; SizeArea_mm2: 1.28; AEC Qualified: Y; VDC_V: 75V; AEC Category: Q200; AEC Grade: 0
C1 C4 C5 C17-C20 C59 C61 C63 C139 = CMP-0007334-3: CAP, CERM, 0.1 uF, 16 V, +/- 10%, X5R, 0603; Manufacturer: MuRata; TaMin_C: -55°C; Polarized: N; SizeAreaWB_mm2: 4.68; Value1: Unknown; U/M: EA; Value: 0.1uF; TaMax_C: 85°C; SizeZ_mm: 1; SizeX_mm: 1.6; SizeY_mm: 0.8; SizeArea_mm2: 1.28; Cap_F: 100nF; AEC Category: Q200
C2 C60 C62 = CMP-0081458-1: CAP, CERM, 1 µF, 16 V,+/- 20%, X5R, 0603; Manufacturer: Yageo America; TaMin_C: -55°C; Polarized: N; SizeAreaWB_mm2: 4.68; U/M: EA; Value: 1uF; TaMax_C: 85°C; SizeZ_mm: 1; SizeX_mm: 1.6; SizeY_mm: 0.8; SizeArea_mm2: 1.28; AEC Category: Q200
C3 = CMP-0007334-3: CAP, CERM, 0.1 uF, 16 V, +/- 10%, X5R, 0603; Manufacturer: MuRata; PartNumber: GRM188R61C104KA01D; TaMin_C: -55°C; Polarized: N; SizeAreaWB_mm2: 4.68; Value1: Unknown; U/M: EA; Value: 0.1uF; TaMax_C: 85°C; SizeZ_mm: 1; SizeX_mm: 1.6; SizeY_mm: 0.8; SizeArea_mm2: 1.28; Cap_F: 100nF; AEC Category: Q200
C6 = CMP-0081458-1: CAP, CERM, 1 µF, 16 V,+/- 20%, X5R, 0603; Manufacturer: Yageo America; PartNumber: CC0603MRX5R7BB105; TaMin_C: -55°C; Polarized: N; SizeAreaWB_mm2: 4.68; U/M: EA; Value: 1uF; TaMax_C: 85°C; SizeZ_mm: 1; SizeX_mm: 1.6; SizeY_mm: 0.8; SizeArea_mm2: 1.28; AEC Category: Q200
C12 = CMP-0007138-2: CAP, CERM, 0.47 uF, 16 V, +/- 10%, X7R, AEC-Q200 Grade 1, 0603; Manufacturer: MuRata; TaMin_C: -55°C; Polarized: N; SizeAreaWB_mm2: 4.68; Value1: Unknown; U/M: EA; Value: 0.47uF; TaMax_C: 125°C; SizeZ_mm: 1; SizeX_mm: 1.6; SizeY_mm: 0.8; SizeArea_mm2: 1.28; AEC Qualified: Y; AEC Category: Q200
C14 = CMP-0006977-1: CAP, CERM, 0.01 uF, 100 V, +/- 10%, X7R, 0603; Manufacturer: Kemet; TaMin_C: -55°C; Polarized: N; SizeAreaWB_mm2: 4.68; Value1: Unknown; U/M: EA; Value: 0.01uF; TaMax_C: 125°C; SizeZ_mm: 1; SizeX_mm: 1.6; SizeY_mm: 0.8; SizeArea_mm2: 1.28; AEC Category: Q200
C15 C16 C25 C26 = CMP-0006439-2: CAP, CERM, 22 pF, 50 V, +/- 5%, C0G/NP0, 0402; Manufacturer: MuRata; TaMin_C: -55°C; Polarized: N; SizeAreaWB_mm2: 3; Value1: Unknown; U/M: EA; Value: 22pF; TaMax_C: 125°C; SizeZ_mm: 0.6; SizeX_mm: 1; SizeY_mm: 0.5; Value2: 50V; AEC Category: Q200
C23 = CMP-0079154-1: CAP, CERM, 1 µF, 16 V,+/- 10%, X7R, AEC-Q200 Grade 1, 0603; Manufacturer: MuRata; SizeAreaWB_mm2: 4.68; SizeArea_mm2: 1.28; AEC Qualified: Y; AEC Category: Q200; Value: 1uF; TaMax_C: 125°C; SizeZ_mm: 1; Polarized: N; TaMin_C: -55°C; SizeY_mm: 0.8; U/M: EA; SizeX_mm: 1.6
C24 = CMP-0007006-5: CAP, CERM, 1 uF, 25 V, +/- 10%, X5R, 0603; Manufacturer: TDK; TaMin_C: -55°C; Polarized: N; SizeAreaWB_mm2: 4.68; Value1: Unknown; U/M: EA; Value: 1uF; TaMax_C: 85°C; SizeZ_mm: 1; SizeX_mm: 1.6; SizeY_mm: 0.8; Value2: 25V; SizeArea_mm2: 1.28; Cap_F: 1µF; AEC Category: Q200
C68 = GRM188R71H104KA93D: CAP, CERM, 0.1 µF, 50 V,+/- 10%, X7R, 0603; Manufacturer: MuRata; Polarized: N; CompType: Capacitor; Value: 0.1uF; U/M: EA; Cap_F: 0.0000001; Tolerance_%: 10; VDC_V: 50; Value2: 50V; TaMin_C: -55; TaMax_C: 125; Cap_Case: 0603; SizeArea_mm2: 1.28; SizeAreaWB_mm2: 4.68; SizeX_mm: 1.6; SizeY_mm: 0.8; SizeZ_mm: 1; AEC Category: Q200; Green_Lifecycle: Active; Green_REACh: Passed
C138 = CMP-0007122-5: CAP, CERM, 10 uF, 16 V, +/- 20%, X5R, 0603; Manufacturer: Taiyo Yuden; TaMin_C: -55°C; Polarized: N; SizeAreaWB_mm2: 4.68; Value1: Unknown; U/M: EA; Value: 10uF; TaMax_C: 85°C; SizeZ_mm: 1; SizeX_mm: 1.6; SizeY_mm: 0.8; SizeArea_mm2: 1.28; Cap_F: 10µF; AEC Category: Q200
C140 C148 = CMP-0007434-4: CAP, CERM, 0.1 uF, 50 V, +/- 10%, X7R, 0603; Manufacturer: MuRata; TaMin_C: -55°C; Polarized: N; SizeAreaWB_mm2: 4.68; Value1: Unknown; U/M: EA; Value: 0.1uF; TaMax_C: 125°C; SizeZ_mm: 1; SizeX_mm: 1.6; SizeY_mm: 0.8; SizeArea_mm2: 1.28; AEC Category: Q200
D17 = CMP-0028868-1: Diode, Schottky, 20 V, 0.5 A, SOD-323F; Manufacturer: Panasonic; Io_A: 500mA; Green_Lifecycle: Not Set; SizeAreaWB_mm2: 7.875; Vr_V: 20V; Green_REACh: Incomplete; Value1: 0.5A; TJmax_C: 125°C; U/M: EA; Value: 20V; SizeZ_mm: 0.8; SizeX_mm: 2.5; SizeY_mm: 1.25; Vf_V: 500mV; Value2: 0.5V; SizeArea_mm2: 3.125; AEC Qualified: N; AEC Category: Q101
D18 = CMP-0005782-3: Diode, Zener, 3.6 V, 500 mW, SOD-123; Manufacturer: ON Semiconductor; Value1: 0.5W; SizeZ_mm: 1.35; Power_W: 500mW; SizeX_mm: 3.85; SizeY_mm: 1.7; SizeAreaWB_mm2: 13.095; RJA_CperW: 340; AEC Category: Q101; SizeArea_mm2: 6.545
D49-D57 = CMP-0005601-2: Diode, TVS, Bi, 7 V, SMB; Manufacturer: Littelfuse; SizeZ_mm: 2.6; Ppk: 600W; AEC Category: Q101; SizeArea_mm2: 21.336; SizeX_mm: 5.6; SizeY_mm: 3.81; RJA_CperW: 100; SizeAreaWB_mm2: 44.156
J3 = CMP-0075406-2: as J4 on sheet High Level Sheet
J12 = CMP-0075634-1: Header(Shrouded), 1.27mm, 5x2, Gold, SMT; Manufacturer: Samtec; Pitch_mm: 1.27; Gender: Male; Cert_CSA: Y; Current_A: 3.3A; CT: False; Row_Count: 2
L2 L5 = CMP-0122125-1: 51 µH @ 100 kHz 2 Line Common Mode Choke Surface Mount 2.6 kOhms @ 10 MHz 200mA DCR 700mOhm; Manufacturer: Bourns; AEC Grade: Grade 0; AEC Qualified: Yes; DCR_ohm: 0.7; Ind_H: 51µH; Material: Ferrite; SizeZ_mm: 2.5mm; Impedance At Frequency: 2600Ω @ 10MHz; Shrouded: true; Test Frequency: 100kHz; Tolerance_%: -30/+50%
L3 L4 L6-L9 = CMP-0003196-2: Ferrite Bead, 600 ohm @ 100 MHz, 0.2 A, 0603; Manufacturer: Wurth Elektronik; Ztyp@1GHz_Ohm: 223.805; ZTyp@100MHz_Ohm: 600; SizeAreaWB_mm2: 4.68; DCR_ohm: 0.45; Value1: 0.45 ohm; Value: 600 ohm; Imax_A: 200mA; SizeZ_mm: 1; SizeX_mm: 1.6; SizeY_mm: 0.8; Value2: 0.2A; SizeArea_mm2: 1.28
LED1 = CMP-0074720-1: LED, RGB, SMD; Manufacturer: Everlight; Io_A: 25mA; Vr_V: 5V; Tjmax_C: 85°C; Value1: W; U/M: EA; Angle: 120.0; Ir_A: 50µA; Vf_V: 3.8V
Q66 = CMP-0000338-1: Transistor, PNP, 80 V, 0.5 A, SOT-23; Manufacturer: ON Semiconductor; TaMax_C: 150°C; Value1: 0.5 A; Vcesat1_V: 250mV; SizeX_mm: 2.5; SizeY_mm: 3; TaMin_C: -55°C; IcRated_A: 500mA; CompType: BJT; SizeZ_mm: 1.1; Value: 80 V; SizeArea_mm2: 7.5; NPN: 0; Vceo_V: 80V; PNP: 1; AEC Category: Q101; SizeAreaWB_mm2: 14; U/M: EA
R5 R28 R30 R45 R52 R192 = CMP-0021998-4: RES, 10.0 k, 1%, 0.1 W, AEC-Q200 Grade 0, 0603; Manufacturer: Vishay-Dale; Power_W: 100mW; TempCo: 100 ppm/C; Value_Code: 10k0; Value: 10.0k; EIA_Code: E96; Res_ohm: 10k; SizeX_mm: 1.6; SizeY_mm: 0.8; SizeZ_mm: 1; Value2: 0.1W; SizeArea_mm2: 1.28; AEC Qualified: Y; VDC_V: 75V; AEC Category: Q200; AEC Grade: 0
R6 R7 R11 R12 R14-R16 R18 R19 R22 R27 R31 R35-R40 R46 R51 R53 R54 = CMP-0021991-2: RES, 100, 1%, 0.1 W, 0603; Manufacturer: Vishay-Dale; Power_W: 100mW; TempCo: 100 ppm/C; Value_Code: 100R; U/M: EA; Value: 100; EIA_Code: E96; SizeX_mm: 1.6; SizeY_mm: 0.8; SizeZ_mm: 1; Value2: 0.1W; SizeArea_mm2: 1.28; VDC_V: 75V; AEC Category: Q200
R8 = CMP-0022438-1: RES, 47.0 k, 1%, 0.1 W, AEC-Q200 Grade 0, 0603; Manufacturer: Vishay-Dale; Power_W: 100mW; TempCo: 100 ppm/C; Value_Code: 47k0; U/M: EA; Value: 47.0k; Res_ohm: 47k; SizeX_mm: 1.6; SizeY_mm: 0.8; SizeZ_mm: 1; Value2: 0.1W; SizeArea_mm2: 1.28; AEC Qualified: Y; VDC_V: 75V; AEC Grade: 0; AEC Category: Q200
R9 R10 R17 R20 = CMP-0023213-5: RES, 60.4, 1%, 0.1 W, 0603; Manufacturer: Yageo; Power_W: 100mW; TempCo: 100 ppm/C; Value_Code: 60R4; Value: 60.4; EIA_Code: E96; SizeX_mm: 1.6; SizeY_mm: 0.8; SizeZ_mm: 1; Value2: 0.1W; SizeArea_mm2: 1.28; AEC Qualified: N; VDC_V: 75V; AEC Category: Q200; SizeAreaWB_mm2: 4.68
R13 = CRCW04020000Z0ED: RES, 0, 5%, 0.063 W, 0402; Manufacturer: Vishay-Dale; CompType: Resistor; Value: 0; Value_Code: 0000; Tolerance_%: 5; Power_W: 0.063; Value2: 0.063W; VDC_V: 50; TempCo: 200 ppm/C; SizeArea_mm2: 0.5; SizeX_mm: 1; SizeZ_mm: 0.6; EIA_Code: E24; U/M: EA; AEC Category: Q200; Green_Lifecycle: Active; Green_REACh: Passed
R21 = CMP-0088648-1: Res Thin Film 0402 100K Ohm 0.1% 1/16W ±25ppm/°C Molded SMD SMD Punched Carrier T/R; Manufacturer: Panasonic; Category 7542B8484461Ae85: Passive Components; VDC_V: 50V; Category Cd01000Bfc2916C6: Single Components; Power_W: 63mW; Category 5A00970A6D5C81C7: Uncategorized; AEC Qualified: Yes; SizeZ_mm: 0.4mm; Voltage: 25V; AEC Grade: Grade 0; Category 5C6A91606D4187Ad: Resistors
R23 = CMP-0026878-1: RES, 220, 5%, 0.063 W, 0402; Manufacturer: Vishay-Dale; Power_W: 63mW; TempCo: 200 ppm/C; Value_Code: 220R; U/M: EA; Value: 220; EIA_Code: E24; SizeX_mm: 1; SizeY_mm: 0.5; SizeZ_mm: 0.6; Value2: 0.063W; VDC_V: 50V; AEC Category: Q200
R24 R25 = CMP-0026906-1: RES, 330, 5%, 0.063 W, 0402; Manufacturer: Vishay-Dale; Power_W: 63mW; TempCo: 200 ppm/C; Value_Code: 330R; U/M: EA; Value: 330; EIA_Code: E24; SizeX_mm: 1; SizeY_mm: 0.5; SizeZ_mm: 0.6; Value2: 0.063W; VDC_V: 50V; AEC Category: Q200
R26 = CMP-0022248-4: RES, 26.1 k, 1%, 0.1 W, AEC-Q200 Grade 0, 0603; Manufacturer: Vishay-Dale; Power_W: 100mW; TempCo: 100 ppm/C; Value_Code: 26k1; Value: 26.1k; EIA_Code: E96; SizeX_mm: 1.6; SizeY_mm: 0.8; SizeZ_mm: 1; Value2: 0.1W; SizeArea_mm2: 1.28; AEC Qualified: Y; VDC_V: 75V; AEC Category: Q200; AEC Grade: 0
R29 = RC0603FR-07120RL: RES, 120, 1%, 0.1 W, 0603; Manufacturer: Yageo America; CompType: Resistor; Value: 120; Value_Code: 120R; Tolerance_%: 1; Power_W: 0.1; Value2: 0.1W; VDC_V: 150; TempCo: 200 ppm/C; SizeArea_mm2: 1.28; SizeX_mm: 1.6; SizeY_mm: 0.8; U/M: EA; AEC Category: Q200; Green_Lifecycle: Active; Green_REACh: Passed
R32 = CMP-0023653-3: RES, 10.0 k, 0.1%, 0.1 W, 0603; Manufacturer: Yageo America; Power_W: 100mW; TempCo: 25 ppm/C; Value_Code: 10k0; U/M: EA; Value: 10.0k; EIA_Code: E192; Res_ohm: 10k; SizeX_mm: 1.6; SizeY_mm: 0.8; SizeZ_mm: 1; Value2: 0.1W; SizeArea_mm2: 1.28; VDC_V: 75V; AEC Category: Q200
R33 = CMP-0022200-2: RES, 200 k, 1%, 0.1 W, 0603; Manufacturer: Vishay-Dale; Power_W: 100mW; TempCo: 100 ppm/C; U/M: EA; Value: 200k; EIA_Code: E96; SizeX_mm: 1.6; SizeY_mm: 0.8; SizeZ_mm: 1; Value2: 0.1W; SizeArea_mm2: 1.28; VDC_V: 75V; AEC Category: Q200
R34 = CMP-0023037-5: RES, 33.0 k, 1%, 0.1 W, 0603; Manufacturer: Yageo; Power_W: 100mW; TempCo: 100 ppm/C; Value_Code: 33k0; Value: 33.0k; Res_ohm: 33k; SizeX_mm: 1.6; SizeY_mm: 0.8; SizeZ_mm: 1; Value2: 0.1W; SizeArea_mm2: 1.28; AEC Qualified: N; VDC_V: 75V; AEC Category: Q200; SizeAreaWB_mm2: 4.68
R41-R44 = CMP-0023153-5: RES, 4.70 k, 1%, 0.1 W, 0603; Manufacturer: Yageo; Power_W: 100mW; TempCo: 100 ppm/C; Value_Code: 4k70; Value: 4.70k; Res_ohm: 4.7k; SizeX_mm: 1.6; SizeY_mm: 0.8; SizeZ_mm: 1; Value2: 0.1W; SizeArea_mm2: 1.28; AEC Qualified: N; VDC_V: 75V; AEC Category: Q200; SizeAreaWB_mm2: 4.68
RT1 = CMP-0084566-1: Thermistor, DEC0002A (X1SON-2); Alternate Manufacturer: Texas Instruments; Alternate PartNumber: TMP6131DECT; CompType: IC; AEC Category: Q200; SizeX_mm: 1; AEC Qualified: N; SizeZ_mm: 0.5; SizeArea_mm2: 0.6; SizeAreaWB_mm2: 3.2
S1 = CMP-0002210-1: Switch, Tactile, SPST-NO, 0.05A, 12V, SMD; Manufacturer: C&K Components; CurrentRating_mA: 50A; PositionCount: 1; SwitchFunction: Off-Mom
S2 = CMP-0002221-2: Switch, SPST, Off-On, 2 Pos, SMD; Manufacturer: Wurth Elektronik; CurrentRating_mA: 25A; PositionCount: 2; VDC_V: 24V
TP3 TP8 = CMP-0003825-1: 1mm Test Point, SMT; Manufacturer: Any
U1 U4 = CMP-0078146-3: Isolated CAN Transceiver With 70-V Bus Fault Protection and Flexible Data Rate, DW0016B (SOIC-16); Alternate Manufacturer: Texas Instruments; CompType: IC; SizeX_mm: 10.4; SizeArea_mm2: 107.12; Rating: Catalog; SizeZ_mm: 2.65; AEC Category: Q200; AEC Qualified: N; SizeAreaWB_mm2: 152.52; SizeY_mm: 10.3
U2 = CMP-0043108-1: Low-Capacitance + / - 15-kV ESD Protection Array for High-Speed Data Interfaces, 4 Channels, -40 to +85 degC, 6-pin SOT-23 (DBV), Green (RoHS & no Sb/Br); Manufacturer: Texas Instruments; IO Leakage Current(nA): 1.5; SubFamily: ESD Solution; Serial ATA / eSATA: TRUE; IEC 61000-4-2 Air-Gap(+/- kV): 15; Breakdown Voltage(Min)(V): 11; IEC 61000-4-2 Contact(+/- kV): 8
U3 U5 = CMP-0093261-1: 24-V, 2-Channel ESD Protection Diode for In-Vehicle Networks; Manufacturer: Texas Instruments; Cap_F: 3pF; Breakdown Voltage: 25.5V; Clamping Voltage: 32V; TaMax_C: +150°C; Direction: Bidirectional; TaMin_C: -55°C; Ipp: 3.5A; VRWM: 24V; Standoff Height: 0.01mm; SizeZ_mm: 1.12mm; Ppk: 147W; AEC Qualified: No; Number Of Channels: 2
U6 = CMP-0081937-2: 5-kVRMS Reinforced and Basic Isolated RS-485/RS-422 Transceiver With Robust-EMC, DW0016B (SOIC-16); Alternate Manufacturer: Texas Instruments; SizeZ_mm: 2.65; SizeY_mm: 10.3; SizeArea_mm2: 107.12; CompType: IC; AEC Qualified: N; SizeAreaWB_mm2: 152.52; AEC Category: Q200; SizeX_mm: 10.4
U7 = CMP-0043100-2: ESD Protection Array for AC Signal Data Interface, 2 Channels, -40 to +85 degC, 3-pin SC70 (DCK), Green (RoHS & no Sb/Br); Manufacturer: Texas Instruments; IO Leakage Current(nA): 50; IEC 61000-4-2 Contact(+/- kV): 8; IO Capacitance(Typ)(pF): 15; Breakdown Voltage(Min)(V): +/-14; SubFamily: ESD Solution; AEC Category: Q200; AEC Qualified: N; CompType: IC; SizeAreaWB_mm2: 9.3; SizeArea_mm2: 4.2; SizeX_mm: 2.1; SizeY_mm: 2; SizeZ_mm: 1.1
U8 = CMP-0094636-1: Manufacturer: Texas Instruments; Min Supply Voltage: 1.71V; TJmax_C: +150°C; Max Supply Voltage: 5.5V; Standoff Height: 0.1mm; TaMax_C: +125°C; SizeZ_mm: 2.65mm; Interface: SPI,CAN,RS-232,RS-485; TaMin_C: -40°C; AEC Qualified: No
U9 = CMP-0091761-1: Manufacturer: Texas Instruments; TaMin_C: -40°C; AEC Qualified: No; Standoff Height: 0.11mm; Min Supply Voltage: 2.25V; SizeZ_mm: 1.75mm; Nominal Supply Current: 2.7-5.3mA; Interface: I2C; TaMax_C: +125°C; TJmax_C: +150°C; Max Supply Voltage: 5.5V
U31 = CMP-0093960-1: Mixed-Signal Microcontrollers With CAN-FD Interface LQFP64; Part Number: MSPM0G3507SPM; Manufacturer: Texas Instruments; Number Of I2C Channels: 2; Frequency_Fixed: 80MHz; Number Of Cores: 1; Number Of Pwm Channels: 14; Data Bus Width: 32bits; Standoff Height: 0.05mm; SizeZ_mm: 1.6mm; Number Of I/Os: 60; Memory Type: FLASH; Min Supply Voltage: 1.62V; Number Of Adc Channels: 16; Memory Size: 128KBytes; TJmax_C: +130°C; Number Of Uart Channels: 4; Number Of Timers/Counters: 7; Max Supply Voltage: 3.6V; TaMin_C: -40°C; Core Architecture: ARM Cortex-M0+; Interface: I2C,SPI,UART,CAN,LIN,IrDA,SMBus; Ram Size: 32KBytes; AEC Qualified: No; TaMax_C: +125°C
U32-U34 = CMP-0043093-4: Single-Channel ESD in 0402 Package With 10pF Capacitance and 6V Breakdown, DPY0002A (X1SON-2); Alternate PartNumber: TPD1E10B06DPYT; Manufacturer: Texas Instruments; IO Leakage Current(nA): 10; CompType: IC; SizeAreaWB_mm2: 3.2; SizeX_mm: 1.0; SizeY_mm: 0.6; Green_REACh: Passed; AEC Category: Q200; SizeZ_mm: 0.45; IEC 61000-4-2 Air-Gap(+/- kV): 30; Breakdown Voltage(Min)(V): 6; Rating: Catalog; Green_Lifecycle: Active; Eco-Plan: TBD; AEC Qualified: N
Y1 = CMP-0004693-2: Crystal, 32.768 KHz, 12.5 pF, SMD; Manufacturer: Epson; TaMax_C: 85°C; TaMin_C: -40°C; U/M: EA
Y2 = CMP-0098168-2: Crystal 40MHz ±10ppm (Tol) ±20ppm (Stability) 12pF FUND 40Ohm 4-Pin Mini-CSMD T/R; Manufacturer: Seiko Epson; SizeZ_mm: 0.6mm; AEC Qualified: No; Esr: 40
